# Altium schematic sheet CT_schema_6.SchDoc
size 375 x 245 mm
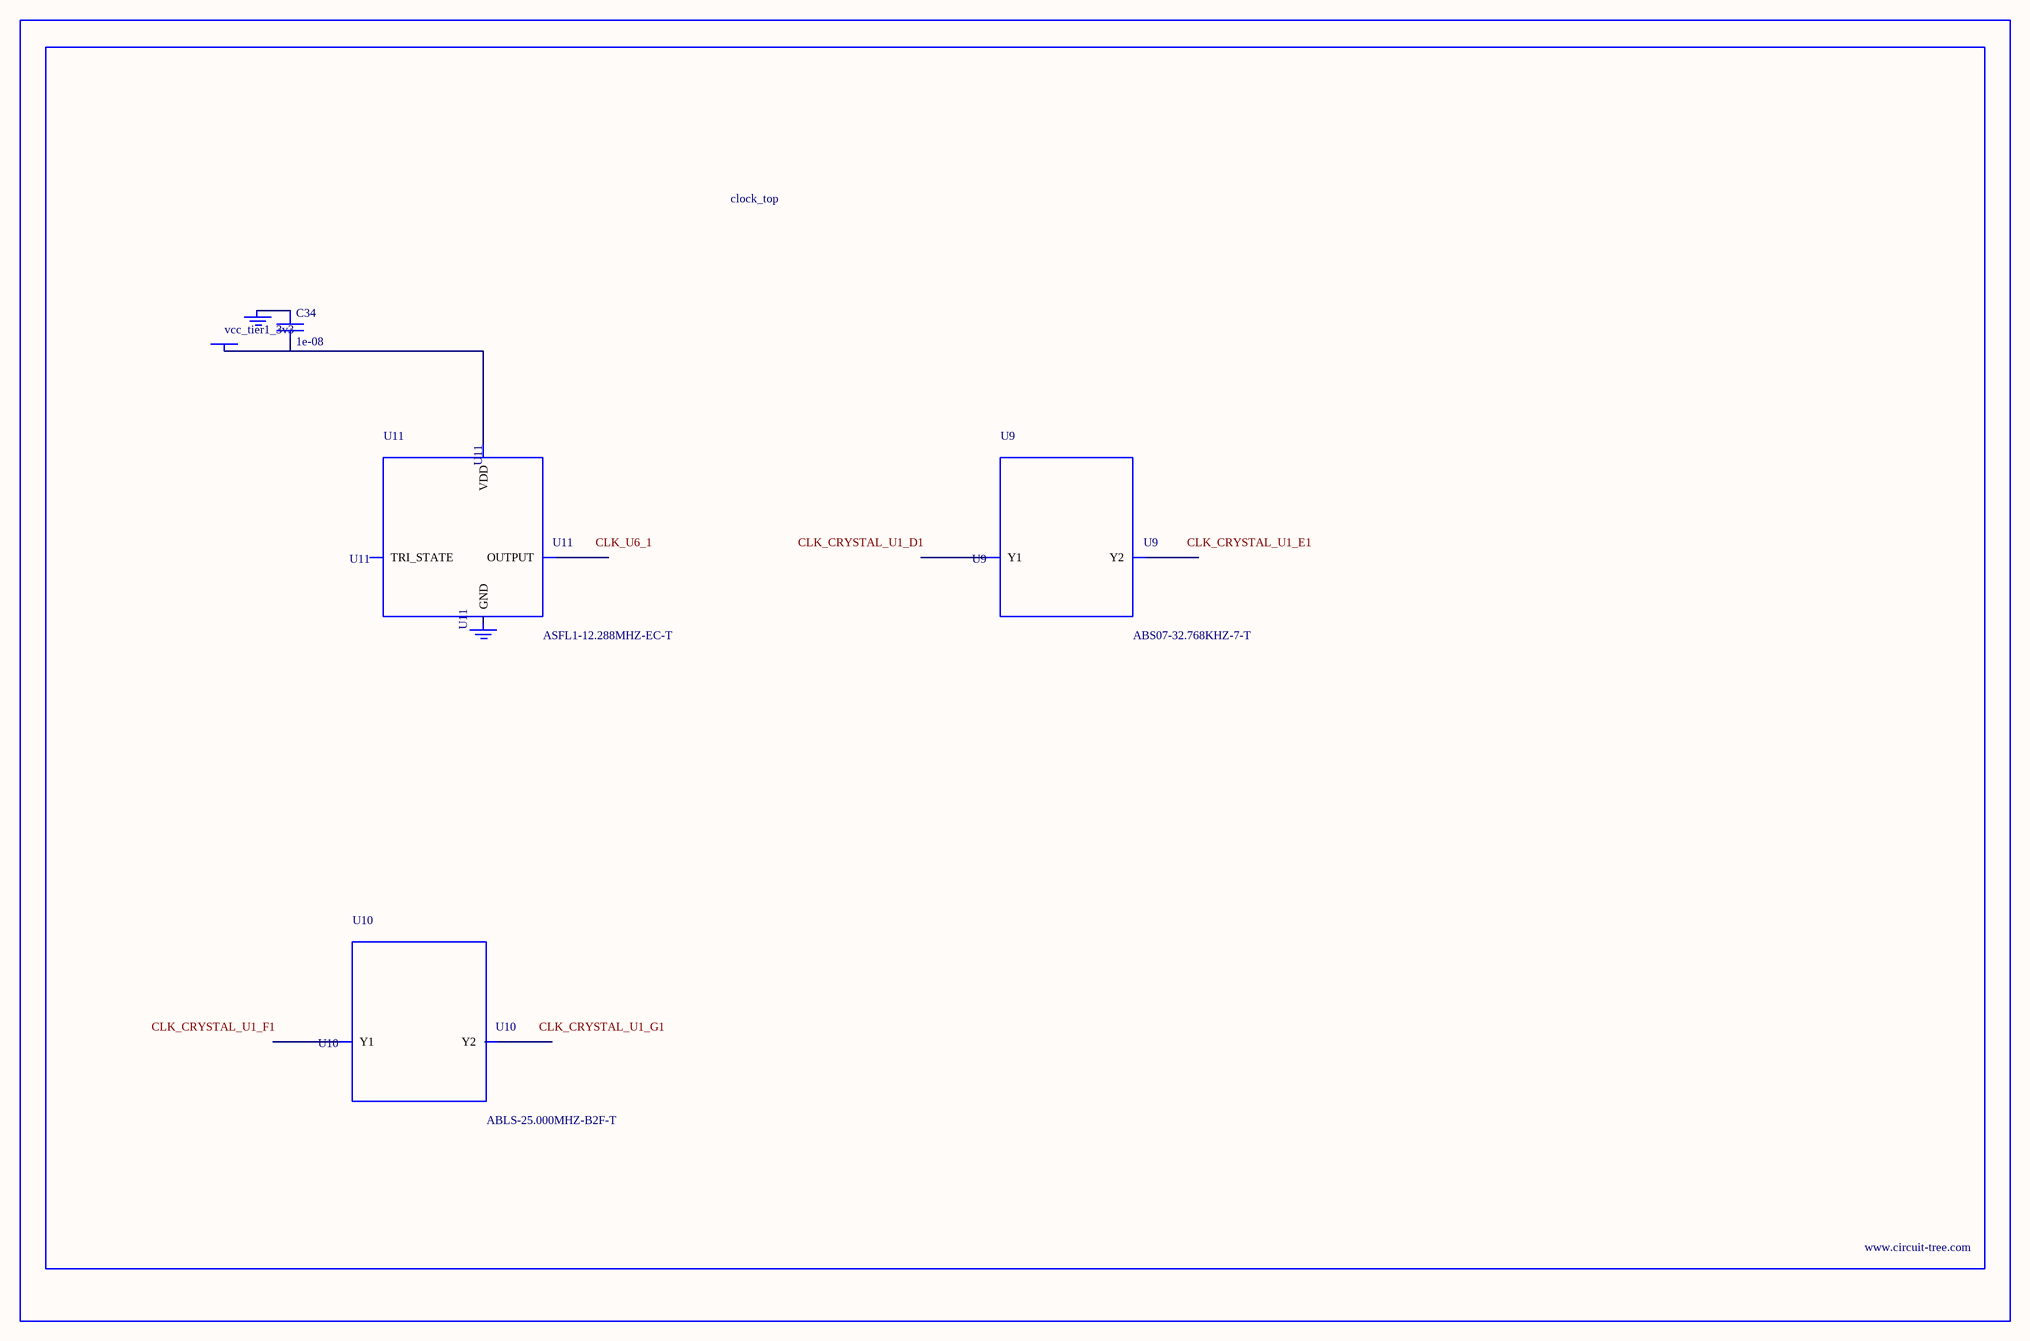
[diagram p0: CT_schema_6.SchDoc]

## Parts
BORDER5  (no value)
C34  1e-08  [C0402]
GND_INSTANCE_5_0  (no value)
GND_INSTANCE_5_1  (no value)
POWER_INSTANCE_5_0  vcc_tier1_3v3
U9  ABS07-32.768KHZ-7-T  [ABS07-32.768KHZ-7-T]
U10  ABLS-25.000MHZ-B2F-T  [ABLS-25.000MHZ-B2F-T]
U11  ASFL1-12.288MHZ-EC-T  [ASFL1]

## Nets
NetC34_1: C34.1 GND_INSTANCE_5_0.0(GND)
NetC34_2: C34.2 POWER_INSTANCE_5_0.0(PWR) U11.4(VDD)

Not connected (* = marked no-connect by the designer): GND_INSTANCE_5_1 0(GND); U9 1(Y1) 2(Y2); U10 1(Y1) 2(Y2); U11 1(TRI_STATE) 2(GND) 3(OUTPUT)

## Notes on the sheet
- Labels drawn without touching a wire or pin: CLK_CRYSTAL_U1_D1, CLK_CRYSTAL_U1_E1, CLK_CRYSTAL_U1_F1, CLK_CRYSTAL_U1_G1, CLK_U6_1

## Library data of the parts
BORDER5 = BORDER_PAGE5
C34 = C0402C103K3RAC
GND_INSTANCE_5_0 GND_INSTANCE_5_1 = GND
POWER_INSTANCE_5_0 = PWR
